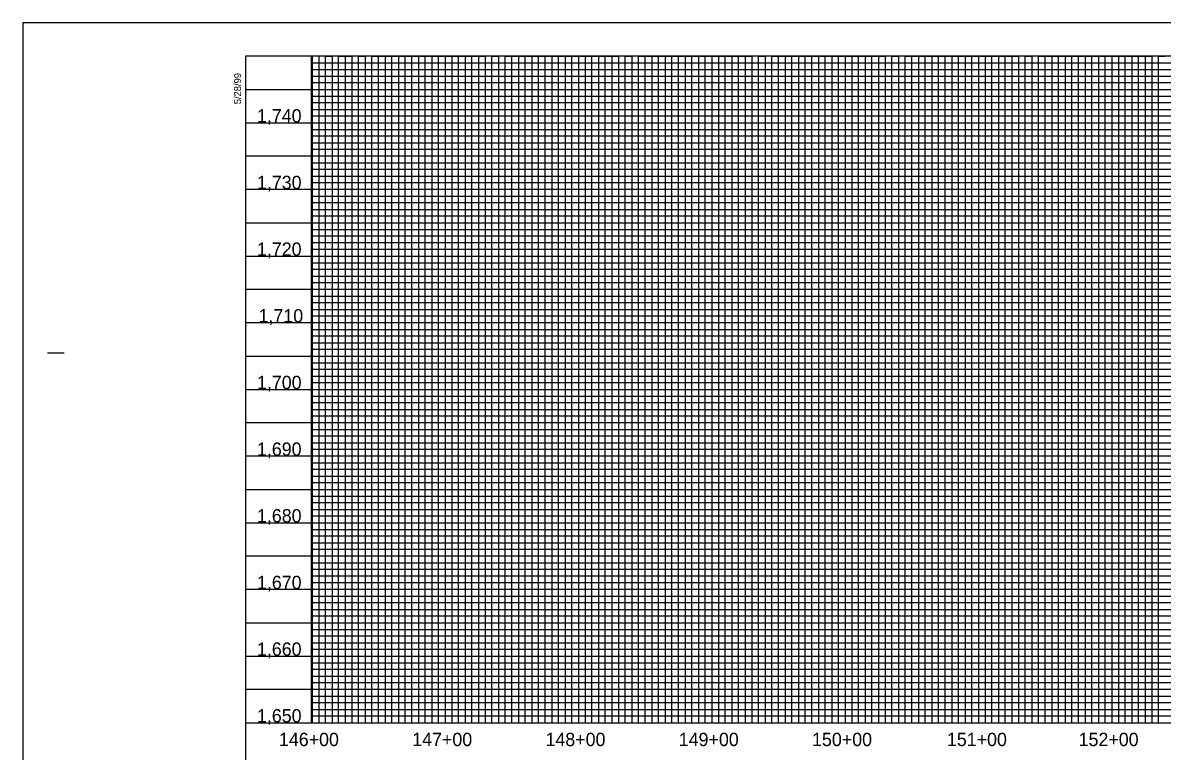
# Model space of a CAD drawing. Extents: x 505602 to 507286, y 483109 to 484209.
# Drawn here: x 505602 to 506457, y 483662 to 484209 of the extents above; entities that cross this region are included whole.
import ezdxf

# ---------------------------------------------------------------- set-up
doc = ezdxf.new("R2010")
doc.units = 0
for name, color, linetype in [('Exist Vertical Profile Vertical Axis Label', 7, 'Continuous'), ('Scratch_Level_4', 7, 'Continuous'), ('Sheet Layout Profile Border Port 1', 7, 'Continuous'), ('Sheet Plot Border Outside CELL', 7, 'Continuous'), ('Sheet Profile CELL', 7, 'Continuous'), ('Sheet Profile Grid Major CELL', 7, 'Continuous'), ('Sheet Profile Grid Middle CELL', 7, 'Continuous'), ('Sheet Profile Grid Minor CELL', 7, 'Continuous')]:
    doc.layers.add(name, color=color, linetype=linetype)

msp = doc.modelspace()

# ---------------------------------------------------------------- linework, layer by layer
at = {"layer": 'Scratch_Level_4'}
msp.add_line((505818.69, 483683.71), (505818.69, 484183.71), dxfattribs=at)
msp.add_lwpolyline([(507269.08, 483683.71), (507269.07, 484022.66), (507069.03, 484022.66), (507069.03, 484142), (507016.54, 484142), (507016.54, 484183.71), (505818.69, 484183.71), (505818.69, 483683.71)], close=True, dxfattribs=at)
at = {"layer": 'Sheet Layout Profile Border Port 1'}
msp.add_lwpolyline([(505819.08, 484183.71), (505819.08, 483683.71), (507069.08, 483683.71), (507269.07, 484022.66), (507269.07, 484022.66), (507069.08, 484183.71)], close=True, dxfattribs=at)
at = {"layer": 'Sheet Plot Border Outside CELL'}
msp.add_lwpolyline([(505602.08, 483108.71), (507286.08, 483108.71), (507286.08, 484208.71), (505602.08, 484208.71)], close=True, dxfattribs=at)
at = {"layer": 'Sheet Profile CELL'}
for p, q in [((505620.58, 483961.21), (505633.08, 483961.21)), ((505769.08, 483683.71), (507269.08, 483683.71))]:
    msp.add_line(p, q, dxfattribs=at)
msp.add_lwpolyline([(507269.08, 484183.71), (505769.08, 484183.71), (505769.08, 483133.71), (507269.08, 483133.71)], close=True, dxfattribs=at)
at = {"layer": 'Sheet Profile Grid Major CELL'}
for points in [[(505819.08, 484183.71), (505819.08, 483683.71), (505869.08, 483683.71), (505869.08, 484183.71), (505919.08, 484183.71), (505919.08, 483683.71), (505969.08, 483683.71), (505969.08, 484183.71), (506019.08, 484183.71), (506019.08, 483683.71), (506069.08, 483683.71), (506069.08, 484183.71), (506119.08, 484183.71), (506119.08, 483683.71), (506169.08, 483683.71), (506169.08, 484183.71), (506219.08, 484183.71), (506219.08, 483683.71), (506269.08, 483683.71), (506269.08, 484183.71), (506319.08, 484183.71), (506319.08, 483683.71), (506369.08, 483683.71), (506369.08, 484183.71), (506419.08, 484183.71), (506419.08, 483683.71), (506469.08, 483683.71)], [(505769.08, 484133.71), (507069.08, 484133.71)], [(507069.08, 484083.71), (505769.08, 484083.71), (505769.08, 484033.71), (507069.08, 484033.71)], [(507269.08, 483983.71), (505769.08, 483983.71), (505769.08, 483933.71), (507269.08, 483933.71)], [(507269.08, 483883.71), (505769.08, 483883.71), (505769.08, 483833.71), (507269.08, 483833.71)], [(507269.08, 483783.71), (505769.08, 483783.71), (505769.08, 483783.71), (505769.08, 483733.71), (507269.08, 483733.71)]]:
    msp.add_lwpolyline(points, dxfattribs=at)
at = {"layer": 'Sheet Profile Grid Middle CELL'}
msp.add_line((505769.08, 484158.71), (507069.03, 484158.71), dxfattribs=at)
for points in [[(505844.08, 484183.71), (505844.08, 483683.71), (505894.08, 483683.71), (505894.08, 484183.71), (505944.08, 484183.71), (505944.08, 483683.71), (505994.08, 483683.71), (505994.08, 484183.71), (506044.08, 484183.71), (506044.08, 483683.71), (506094.08, 483683.71), (506094.08, 484183.71), (506144.08, 484183.71), (506144.08, 483683.71), (506194.08, 483683.71), (506194.08, 484183.71), (506244.08, 484183.71), (506244.08, 483683.71), (506294.08, 483683.71), (506294.08, 484183.71), (506344.08, 484183.71), (506344.08, 483683.71), (506394.08, 483683.71), (506394.08, 483683.71), (506394.08, 484183.71), (506444.08, 484183.71), (506444.08, 483683.71), (506494.08, 483683.71)], [(507069.08, 484108.71), (505769.08, 484108.71), (505769.08, 484058.71), (507069.08, 484058.71)], [(507269.08, 484008.71), (505769.08, 484008.71), (505769.08, 483958.71), (507094.08, 483958.71)], [(507269.08, 483908.71), (505769.08, 483908.71), (505769.08, 483858.71), (507269.08, 483858.71)], [(507269.08, 483808.71), (505769.08, 483808.71), (505769.08, 483758.71), (507269.08, 483758.71)], [(507269.08, 483708.71), (505769.08, 483708.71)]]:
    msp.add_lwpolyline(points, dxfattribs=at)
at = {"layer": 'Sheet Profile Grid Minor CELL'}
for p, q in [((505819.08, 484178.71), (507069.08, 484178.71)), ((505819.08, 484173.71), (505819.08, 484173.71)), ((507069.08, 484173.71), (505819.08, 484173.36)), ((505819.08, 484168.71), (507069.08, 484168.71)), ((507069.03, 484048.71), (505819.08, 484048.71)), ((507069.08, 484043.71), (505819.08, 484043.71)), ((507069.08, 484038.71), (505819.08, 484038.71)), ((505819.08, 484028.71), (507069.08, 484028.71)), ((507069.08, 484023.71), (505819.08, 484023.71)), ((505819.08, 484018.71), (507219.08, 484018.71)), ((507219.08, 483998.71), (505819.08, 483998.71)), ((505819.08, 483993.71), (507219.08, 483993.71)), ((507219.08, 483973.71), (505819.08, 483973.71)), ((505819.08, 483968.71), (507219.08, 483968.71)), ((507219.08, 483948.71), (505819.08, 483948.71)), ((505819.08, 483943.71), (507219.08, 483943.71)), ((507219.08, 483938.71), (505819.08, 483938.71)), ((505819.08, 483928.71), (507219.08, 483928.71)), ((507219.08, 483923.71), (505819.08, 483923.71)), ((505819.08, 483918.71), (507219.08, 483918.71)), ((507219.08, 483913.71), (505819.08, 483913.71)), ((505819.08, 483903.71), (507219.08, 483903.71)), ((507219.08, 483898.71), (505819.08, 483898.71)), ((505819.08, 483893.71), (507219.08, 483893.71)), ((507219.08, 483888.71), (505819.08, 483888.71)), ((505819.08, 483878.71), (507219.08, 483878.71)), ((507219.08, 483873.71), (505819.08, 483873.71)), ((505819.08, 483868.71), (507219.08, 483868.71)), ((507219.08, 483863.71), (505819.08, 483863.71)), ((505819.08, 483853.71), (507219.08, 483853.71)), ((507219.08, 483848.71), (505819.08, 483848.71)), ((505819.08, 483843.71), (507219.08, 483843.71)), ((507219.08, 483838.71), (505819.08, 483838.71)), ((505819.08, 483828.71), (507219.08, 483828.71)), ((507219.08, 483823.71), (505819.08, 483823.71)), ((505819.08, 483818.71), (507219.08, 483818.71)), ((507219.08, 483813.71), (505819.08, 483813.71)), ((505819.08, 483803.71), (507219.08, 483803.71)), ((507219.08, 483798.71), (505819.08, 483798.71)), ((507219.08, 483793.71), (505819.08, 483793.71)), ((507219.08, 483788.71), (505819.08, 483788.71)), ((505819.08, 483778.71), (507219.08, 483778.71)), ((507219.08, 483773.71), (505819.08, 483773.71)), ((505819.08, 483768.71), (507219.08, 483768.71)), ((507219.08, 483763.71), (505819.08, 483763.71)), ((505819.08, 483753.71), (507219.08, 483753.71)), ((507219.08, 483748.71), (505819.08, 483748.71)), ((505819.08, 483743.71), (507219.08, 483743.71)), ((507219.08, 483738.71), (505819.08, 483738.71)), ((505819.08, 483728.71), (507219.08, 483728.71)), ((507219.08, 483723.71), (505819.08, 483723.71)), ((505819.08, 483718.71), (507219.08, 483718.71)), ((507219.08, 483713.71), (505819.08, 483713.71)), ((505819.08, 483703.71), (507219.08, 483703.71)), ((507219.08, 483698.71), (505819.08, 483698.71)), ((505819.08, 483693.71), (507219.08, 483693.71))]:
    msp.add_line(p, q, dxfattribs=at)
for points in [[(505824.08, 484183.71), (505824.08, 483683.71), (505829.08, 483683.71), (505829.08, 484183.71), (505834.08, 484183.71), (505834.08, 483683.71), (505839.08, 483683.71), (505839.08, 484183.71), (505849.08, 484183.71), (505849.08, 483683.71), (505854.08, 483683.71), (505854.08, 484183.71), (505859.08, 484183.71), (505859.08, 483683.71), (505864.08, 483683.71), (505874.08, 483683.71), (505879.08, 483683.71), (505879.08, 484183.71), (505884.08, 484183.71), (505884.08, 483683.71), (505889.08, 483683.71), (505889.08, 484183.71), (505899.08, 484183.71), (505899.08, 483683.71), (505904.08, 483683.71), (505904.08, 484183.71), (505909.08, 484183.71), (505909.08, 483683.71), (505914.08, 483683.71), (505914.08, 484183.71), (505924.08, 484183.71), (505924.08, 483683.71), (505929.08, 483683.71), (505929.08, 484183.71), (505934.08, 484183.71), (505934.08, 483683.71), (505939.08, 483683.71), (505939.08, 484183.71), (505949.08, 484183.71), (505949.08, 483683.71), (505954.08, 483683.71), (505954.08, 484183.71), (505959.08, 484183.71), (505959.08, 483683.71), (505964.08, 483683.71), (505964.08, 484183.71), (505974.08, 484183.71), (505974.08, 483683.71), (505979.08, 483683.71), (505979.08, 484183.71), (505984.08, 484183.71), (505984.08, 483683.71), (505989.08, 483683.71), (505989.08, 484183.71), (505999.08, 484183.71), (505999.08, 483683.71), (506004.08, 483683.71), (506004.08, 484183.71), (506009.08, 484183.71), (506009.08, 483683.71), (506014.08, 483683.71), (506014.08, 484183.71), (506024.08, 484183.71), (506024.08, 483683.71), (506029.08, 483683.71), (506029.08, 484183.71), (506034.08, 484183.71), (506034.08, 483683.71)], [(505864.08, 483683.71), (505864.08, 484183.71), (505874.08, 484183.71), (505874.08, 483683.71)], [(506034.08, 483683.71), (506039.08, 483683.71), (506039.08, 484183.71), (506049.08, 484183.71), (506049.08, 483683.71), (506054.08, 483683.71), (506054.08, 484183.71), (506059.08, 484183.71), (506059.08, 483683.71), (506064.08, 483683.71), (506064.08, 484183.71), (506074.08, 484183.71), (506074.08, 483683.71), (506079.08, 483683.71), (506079.08, 484183.71), (506084.08, 484183.71), (506084.08, 483683.71), (506089.08, 483683.71), (506089.08, 484183.71), (506099.08, 484183.71), (506099.08, 483683.71), (506104.08, 483683.71), (506104.08, 484183.71), (506109.08, 484183.71), (506109.08, 483683.71), (506114.08, 483683.71), (506114.08, 484183.71), (506124.08, 484183.71), (506124.08, 483683.71), (506129.08, 483683.71), (506129.08, 484183.71), (506134.08, 484183.71), (506134.08, 483683.71), (506139.08, 483683.71), (506139.08, 484183.71), (506149.08, 484183.71), (506149.08, 483683.71), (506154.08, 483683.71), (506154.08, 484183.71), (506159.08, 484183.71), (506159.08, 483683.71), (506164.08, 483683.71), (506164.08, 484183.71), (506174.08, 484183.71), (506174.08, 483683.71), (506179.08, 483683.71), (506179.08, 484183.71), (506184.08, 484183.71), (506184.08, 483683.71), (506189.08, 483683.71), (506189.08, 484183.71), (506199.08, 484183.71), (506199.08, 483683.71), (506204.08, 483683.71), (506204.08, 484183.71), (506209.08, 484183.71), (506209.08, 483683.71), (506214.08, 483683.71), (506214.08, 484183.71), (506224.08, 484183.71), (506224.08, 483683.71), (506229.08, 483683.71), (506229.08, 484183.71), (506234.08, 484183.71), (506234.08, 483683.71), (506239.08, 483683.71), (506239.08, 484183.71), (506249.08, 484183.71), (506249.08, 483683.71), (506254.08, 483683.71), (506254.08, 484183.71), (506259.08, 484183.71), (506259.08, 483683.71), (506264.08, 483683.71), (506264.08, 484183.71), (506274.08, 484183.71), (506274.08, 483683.71), (506279.08, 483683.71), (506279.08, 484183.71), (506284.08, 484183.71), (506284.08, 483683.71), (506289.08, 483683.71), (506289.08, 484183.71), (506299.08, 484183.71), (506299.08, 483683.71), (506304.08, 483683.71), (506304.08, 484183.71), (506309.08, 484183.71), (506309.08, 483683.71), (506314.08, 483683.71), (506314.08, 484183.71), (506324.08, 484183.71), (506324.08, 483683.71), (506329.08, 483683.71), (506329.08, 484183.71), (506334.08, 484183.71), (506334.08, 483683.71), (506339.08, 483683.71), (506339.08, 484183.71), (506349.08, 484183.71)], [(506349.08, 484183.71), (506349.08, 483683.71), (506354.08, 483683.71), (506354.08, 484183.71), (506359.08, 484183.71), (506359.08, 483683.71), (506364.08, 483683.71), (506364.08, 484183.71), (506374.08, 484183.71), (506374.08, 483683.71), (506379.08, 483683.71), (506379.08, 484183.71), (506384.08, 484183.71), (506384.08, 483683.71), (506389.08, 483683.71), (506389.08, 484183.71), (506399.08, 484183.71), (506399.08, 483683.71), (506404.08, 483683.71), (506404.08, 484183.71), (506409.08, 484183.71), (506409.08, 483683.71), (506414.08, 483683.71), (506414.08, 484183.71), (506424.08, 484183.71), (506424.08, 483683.71), (506429.08, 483683.71), (506429.08, 484183.71), (506434.08, 484183.71), (506434.08, 483683.71), (506439.08, 483683.71), (506439.08, 484183.71), (506449.08, 484183.71), (506449.08, 483683.71), (506454.08, 483683.71), (506454.08, 484183.71), (506459.08, 484183.71)], [(507069.08, 484163.71), (505819.08, 484163.71), (505819.08, 484153.71), (507069.08, 484153.71)], [(507069.03, 484148.71), (505819.08, 484148.71), (505819.08, 484143.71), (507069.08, 484143.71)], [(507069.08, 484138.71), (505819.08, 484138.71), (505819.08, 484128.71), (507069.08, 484128.71)], [(507069.08, 484123.71), (505819.08, 484123.71), (505819.08, 484118.71), (507069.08, 484118.71)], [(507069.08, 484113.71), (505819.08, 484113.71), (505819.08, 484103.71), (507069.08, 484103.71)], [(507069.08, 484098.71), (505819.08, 484098.71), (505819.08, 484093.71), (507069.08, 484093.71)], [(507069.08, 484088.71), (505819.08, 484088.71), (505819.08, 484078.71), (507069.08, 484078.71)], [(507069.08, 484073.61), (505819.18, 484073.61), (505819.18, 484068.71), (507069.08, 484068.71)], [(507069.08, 484063.71), (505819.08, 484063.71), (505819.08, 484053.71), (507069.08, 484053.71)], [(507219.08, 484013.71), (505819.08, 484013.71), (505819.08, 484003.71), (507219.08, 484003.71)], [(507219.08, 483988.71), (505819.08, 483988.71), (505819.08, 483978.71), (507219.08, 483978.71)], [(507219.08, 483963.71), (505819.08, 483963.71), (505819.08, 483953.71), (507219.08, 483953.71)], [(507219.08, 483688.71), (505819.08, 483688.71)]]:
    msp.add_lwpolyline(points, dxfattribs=at)

# ---------------------------------------------------------------- texts
at = {"layer": 'Exist Vertical Profile Vertical Axis Label'}
for s, p in [('1,740', (505777.78, 484133.96)), ('1,730', (505777.78, 484083.96)), ('1,720', (505777.78, 484033.96)), ('1,710', (505778.97, 483983.96)), ('1,700', (505777.78, 483933.96)), ('1,690', (505777.78, 483883.96)), ('1,680', (505777.78, 483833.96)), ('1,670', (505777.78, 483783.96)), ('1,660', (505777.78, 483733.96)), ('1,650', (505777.78, 483683.96)), ('146+00', (505794.26, 483666.21)), ('147+00', (505894.26, 483666.21)), ('148+00', (505994.26, 483666.21)), ('149+00', (506094.26, 483666.21)), ('150+00', (506194.26, 483666.21)), ('151+00', (506295.45, 483666.21)), ('152+00', (506394.26, 483666.21))]:
    msp.add_text(s, height=10, dxfattribs=at).set_placement(p)
at = {"layer": 'Sheet Profile CELL'}
msp.add_text('5/28/99', height=5.25, rotation=90, dxfattribs=at).set_placement((505765.84, 484147.62))

doc.saveas('drawing.dxf')
